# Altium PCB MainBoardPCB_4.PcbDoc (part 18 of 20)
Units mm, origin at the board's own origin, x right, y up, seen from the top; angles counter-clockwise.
Board outline 333.63 x 349.38 mm, 16 copper layers (L1, L2 (GND), L3 (Sign), L4 (GND), L5 (Sign), L6 (PWR/GND), L7(PWR/GND), L8 (Plane_GND), L9 (PWR/GND), L10 (PWR/GND), L11 (PWR/GND), L12 (Sign), L13 (GND), L14 (Sign), L15 (GND), L16), stack 2.502 mm thick; 2205 components, 1648 nets, 8314 pads, 3172 vias.
Unrouted connection lines stored in the file: 5141.
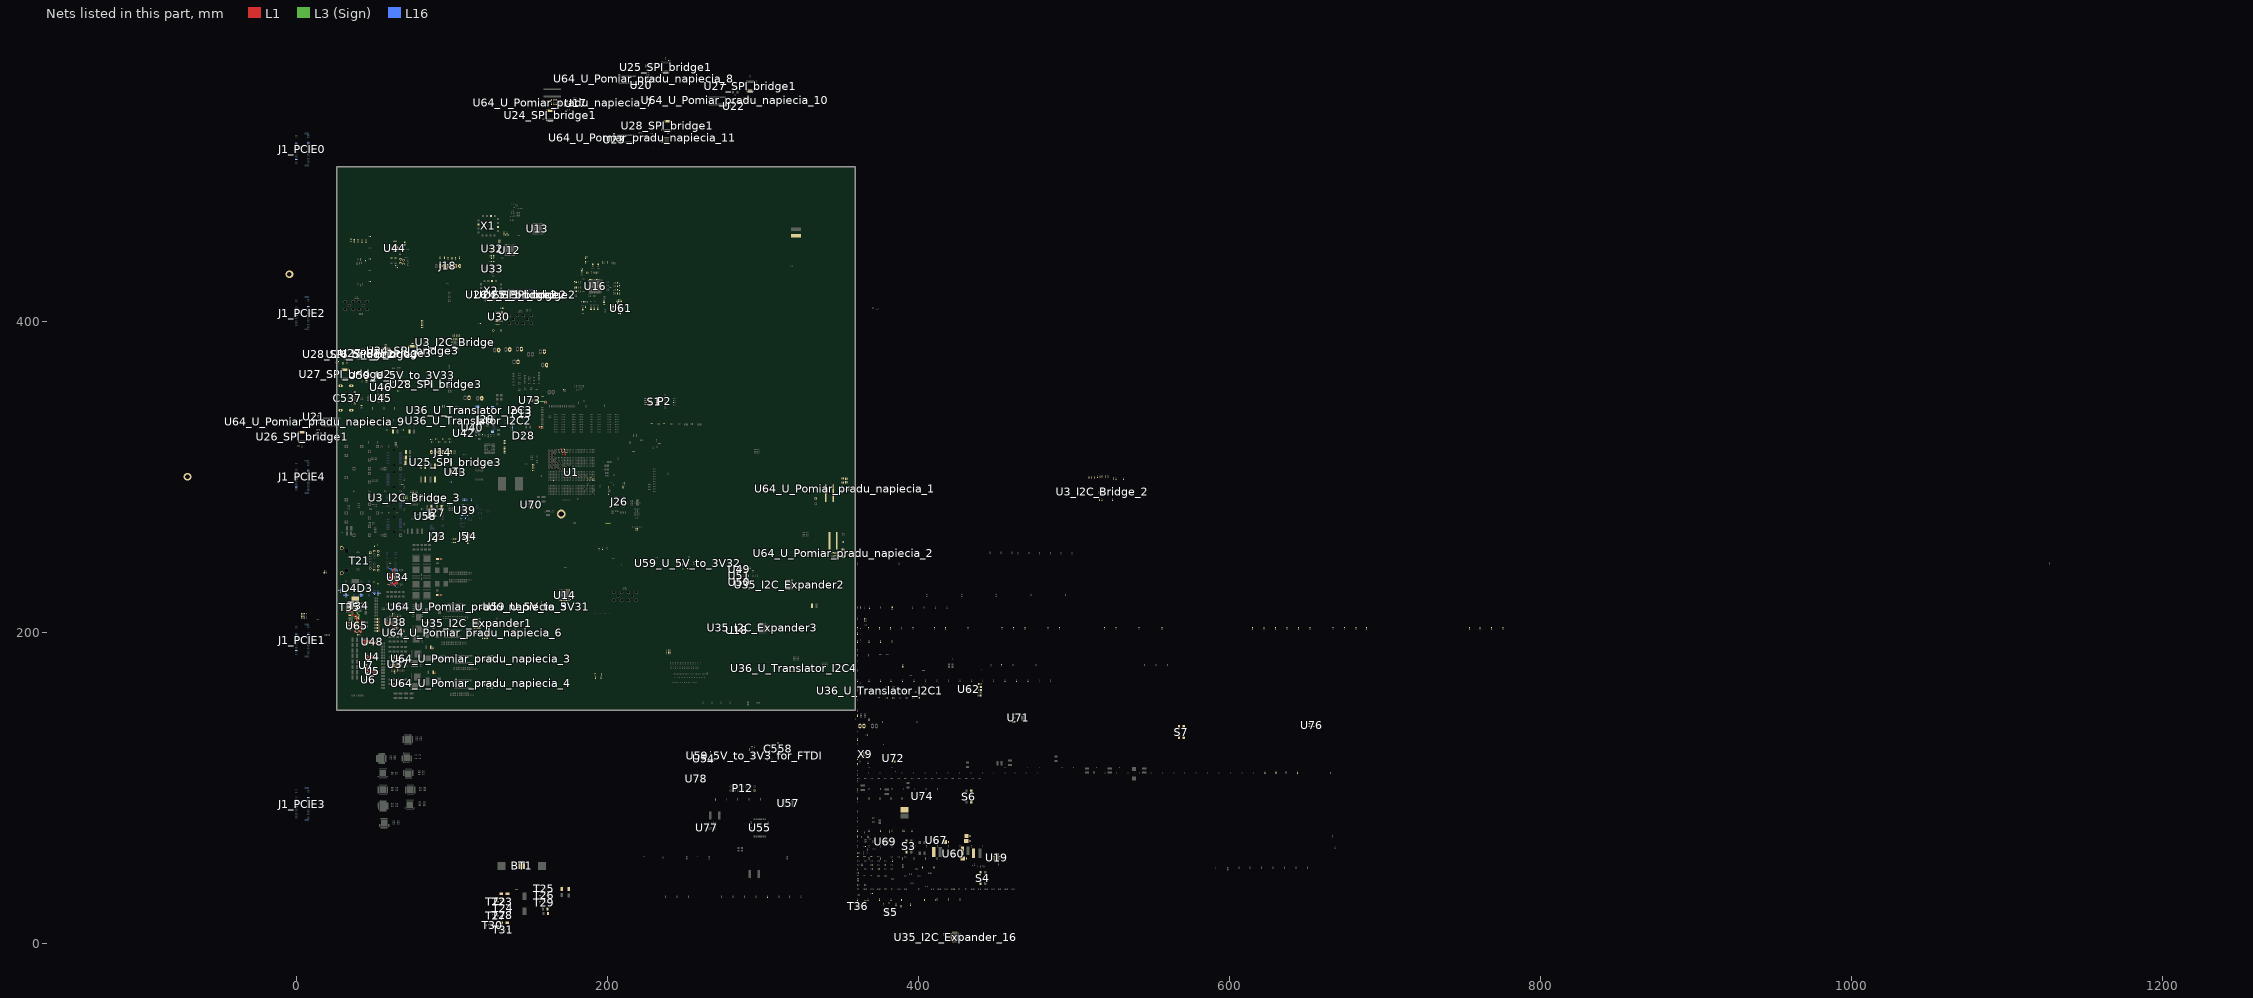
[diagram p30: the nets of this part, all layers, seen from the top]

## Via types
v1: diameter 0.5, hole 0.2, L1 to L16, tented both sides, 1153 vias
v2: diameter 0.5/0.35/0.35/0.35/0.35/0.35/0.35/0.35/0.35/0.35/0.35/0.35/0.35/0.35/0.35/0.5 (per signal layer), hole 0.2, L1 to L16, tented both sides, 548 vias
v3: diameter 0.5, hole 0.2, L1 to L16, 522 vias
v4: diameter 0.5/0.35/0.35/0.35/0.35/0.35/0.35/0.35/0.35/0.35/0.35/0.35/0.35/0.35/0.35/0.5 (per signal layer), hole 0.15, L1 to L16, tented both sides, 266 vias
v5: diameter 0.8, hole 0.4, L1 to L16, tented both sides, 164 vias
v6: diameter 0.35/0/0.35 (per signal layer), hole 0.127, L1 to L3 (Sign), tented both sides, 132 vias
v7: diameter 2.54, hole 1.02, L1 to L16, 125 vias
v8: diameter 1.4, hole 0.5, L1 to L16, tented both sides, 80 vias
v9: diameter 0.35, hole 0.127, L1 to L2 (GND), tented both sides, 36 vias
v10: diameter 0.4, hole 0.2, L1 to L16, 16 vias
v11: diameter 0.25, hole 0.2, L1 to L16, 16 vias
v12: diameter 5, hole 3, L1 to L16, 15 vias
v13: diameter 0.3, hole 0.2, L1 to L16, 15 vias
v14: diameter 0.45, hole 0.15, L1 to L16, 12 vias
v15: diameter 0.5/0.35/0.35/0.35/0.35/0.35/0.35/0.35/0.35/0.35/0.35/0.35/0.35/0.35/0.35/0.45 (per signal layer), hole 0.15, L1 to L16, tented both sides, 10 vias
v16: diameter 0.2/0/0.2 (per signal layer), hole 0.1, L1 to L3 (Sign), tented both sides, 9 vias
v17: diameter 0.4, hole 0.1, L1 to L16, 7 vias
v18: diameter 0.5, hole 0.2, L3 (Sign) to L6 (PWR/GND), tented both sides, 6 vias
v19: diameter 1.65, hole 1.65, L1 to L16, 6 vias
v20: diameter 1.15, hole 1.15, L1 to L16, 6 vias
v21: diameter 0.35/0/0.35 (per signal layer), hole 0.127, L14 (Sign) to L16, tented both sides, 5 vias
v22: diameter 0.2, hole 0.1, L1 to L16, 4 vias
v23: diameter 0.4, hole 0.2, L1 to L16, tented both sides, 2 vias
v24: diameter 0.4, hole 0.15, L1 to L16, 2 vias
v25: diameter 0.508, hole 0.127, L1 to L2 (GND), 2 vias
v26: diameter 0.508, hole 0.127, L2 (GND) to L3 (Sign), 2 vias
v27: diameter 0.5/0.35/0.35/0.35/0.35/0.35/0.35/0.35/0.35/0.35/0.35/0.35/0.35/0.35/0.35/0.5 (per signal layer), hole 0.15, L1 to L16, 2 vias
v28: diameter 0.35, hole 0.127, L3 (Sign) to L6 (PWR/GND), tented both sides, 2 vias
v29: diameter 5.5, hole 3.5, L1 to L16, 1 vias
v30: diameter 0.5/0.35/0.35/0.35/0.35/0.35/0.35/0.35/0.35/0.35/0.35/0.35/0.35/0.35/0.35/0.5 (per signal layer), hole 0.2, L1 to L16, 1 vias
v31: diameter 0.35/0.35/0.35 (per signal layer), hole 0.127, L1 to L3 (Sign), tented both sides, 1 vias
v32: diameter 0.45/0/0.45 (per signal layer), hole 0.15, L1 to L3 (Sign), tented both sides, 1 vias
v33: diameter 0.45/0/0.45 (per signal layer), hole 0.2, L14 (Sign) to L16, tented both sides, 1 vias
v34: diameter 0.35, hole 0.127, L2 (GND) to L3 (Sign), 1 vias
v35: diameter 0.35, hole 0.127, L1 to L2 (GND), 1 vias

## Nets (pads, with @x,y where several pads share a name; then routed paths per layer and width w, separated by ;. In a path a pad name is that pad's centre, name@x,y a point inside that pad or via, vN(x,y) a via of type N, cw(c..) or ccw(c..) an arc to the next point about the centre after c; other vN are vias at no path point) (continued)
Interrupt20: R735.2 U1.AD5 U64_U_Pomiar_pradu_napiecia_11.3
  other v2: 185.397,292.539
LED_0: R329.1 U39.47
LED_0_RJ: R329.2 T21.17
LED_1: R330.1 U39.46
LED_1_RJ: R330.2 T21.18
LED_2: R331.1 U39.45
LED_2_RJ: R331.2 T21.19
LED_3: R332.2 U39.39
LED_3_RJ: R332.1 T21.20
Logic_Out_KEY: R649.2 T26.3
LTC6952_1_CP_Out: C46.2 R77.2 U12.43 X1.2
LTC6952_1_REF_N: C53.1 R81.2 U12.46
LTC6952_1_REF_P: C54.1 R81.1 U12.45
LTC6952_1_Temp: R607.2 U12.49
LTC6952_1_VCO_N: C334.2 R532.2 U12.38
LTC6952_1_VCO_P: R533.1 U12.37
LTC6952_2_REF_N: C42.2 U13.46
LTC6952_2_REF_P: C41.2 U13.45
LTC6952_2_REF_SMA_N: C42.1 J3.2 R75.1
LTC6952_2_REF_SMA_P: C41.1 J2.2 R75.2
LTC6952_2_Temp: R736.2 U13.49
LTC6952_3_REF_N: C44.2 U14.46
LTC6952_3_REF_P: C43.2 U14.45
LTC6952_3_REF_SMA_N: C44.1 J5.2 R76.1
LTC6952_3_REF_SMA_P: C43.1 J4.2 R76.2
LTC6952_3_Temp: R765.2 U14.49
MDC: U39.16
MDIO: R333.2 U39.17
MIO_0: R768.2 U1.H17
  other v2: 169.397,304.539
MIO_1: R769.2
MIO_2: R770.2 U1.A20
  other v2: 162.397,307.539
MIO_3: R771.2 U1.D19
  other v2: 165.397,306.539
MIO_4: R772.2 U1.J17
  other v2: 170.397,304.539
MIO_5: R773.2 U1.C19
  other v2: 164.397,306.539
MIO_6: R774.2 U1.D20
  other v2: 165.397,307.539
MIO_7: R775.2 U1.E19
  other v2: 166.397,306.539
MIO_8: R776.2 U1.E20
  other v2: 166.397,307.539
MIO_9: R777.2 U1.F20
  other v2: 167.397,307.539
MIO_10: R778.2 U1.F18
  other v2: 167.397,305.539
MIO_11: R779.2 U1.G18
  other v2: 168.397,305.539
MIO_12: R780.2 U1.H18
  other v2: 169.397,305.539
MIO_13: R87.1 U1.G19
  other v2: 168.397,306.539
MIO_14: R88.1 U1.E18
  other v2: 166.397,305.539
MIO_15: R89.1 U1.J19
  other v2: 170.397,306.539
MIO_16: R90.1 U1.K17
  other v2: 171.397,304.539
MIO_17: R91.1 U1.C18
  other v2: 164.397,305.539
MIO_18: R92.1 U1.K18
  other v2: 171.397,305.539
MIO_19: R93.1 U1.K16
  other v2: 171.397,303.539
MIO_20: R94.1
MIO_21: R95.1 U1.H19
  other v2: 169.397,306.539
MIO_22: R96.1 U1.F17
  other v2: 167.397,304.539
MIO_23: R781.2 U1.K19
  other v2: 171.397,306.539
MIO_24: R782.2 U1.A18
  other v2: 162.397,305.539
MIO_25: R783.2 U1.B18
  other v2: 163.397,305.539
MIO_26: R784.2 U1.B20
  other v2: 163.397,307.539
MIO_27: R785.2 U1.B21
  other v2: 163.397,308.539
MIO_28: R786.2 U1.A21
  other v2: 162.397,308.539
MIO_29: R787.2 U1.D21
  other v2: 165.397,308.539
MIO_30: R788.2 U1.C21
  other v2: 164.397,308.539
MIO_31: R789.2 U1.A22
  other v2: 162.397,309.539
MIO_32: R790.2 U1.G20
  other v2: 168.397,307.539
MIO_33: R791.2 U1.C22
  other v2: 164.397,309.539
MIO_34: R792.2 U1.B24
  other v2: 163.397,311.539
MIO_35: R793.2 U1.B23
  other v2: 163.397,310.539
MIO_36: R794.2 U1.D22
  other v2: 165.397,309.539
MIO_37: R795.2 U1.F21
  other v2: 167.397,308.539
MIO_38: R796.2 U1.C23
  other v2: 164.397,310.539
MIO_39: R101.1 U1.E22
  other v2: 166.397,309.539
MIO_40: R102.1 U1.C24
  other v2: 164.397,311.539
MIO_41: R103.1 U1.D24
  other v2: 165.397,311.539
MIO_42: R104.1 U1.E23
  other v2: 166.397,310.539
MIO_43: R797.2 U1.F22
  other v2: 167.397,309.539
MIO_44: R798.2 U1.E24
  other v2: 166.397,311.539
MIO_45: R799.2 U1.F23
  other v2: 167.397,310.539
MIO_46: R105.1 U1.K20
  other v2: 171.397,307.539
MIO_47: R107.1 U1.K21
  other v2: 171.397,308.539
MIO_48: R108.1 U1.J21
  other v2: 170.397,308.539
MIO_49: R110.1 U1.G21
  other v2: 168.397,308.539
MIO_50: R111.1 U1.J20
  other v2: 170.397,307.539
MIO_51: R112.1 U1.H21
  other v2: 169.397,308.539
MIO_52: R362.1 U1.A24
  other v2: 162.397,311.539
MIO_53: R800.2 U1.B25
  other v2: 163.397,312.539
MIO_54: R115.1 U1.A23
  other v2: 162.397,310.539
MIO_55: R801.2 U1.B26
  other v2: 163.397,313.539
MIO_56: R116.1 U1.A25
  other v2: 162.397,312.539
MIO_57: R117.1 U1.A26
  other v2: 162.397,313.539
MIO_58: R118.1 U1.A28
  other v2: 162.397,315.539
MIO_59: R119.1 U1.A27
  other v2: 162.397,314.539
MIO_60: R120.1 U1.C26
  other v2: 164.397,313.539
MIO_61: R121.1 U1.B29
  other v2: 163.397,316.539
MIO_62: R122.1 U1.B28
  other v2: 163.397,315.539
MIO_63: R802.2 U1.A29
  other v2: 162.397,316.539
MIO_64: R803.2 U1.B30
  other v2: 163.397,317.539
MIO_65: R804.2 U1.D25
  other v2: 165.397,312.539
MIO_66: R805.2 U1.C27
  other v2: 164.397,314.539
MIO_67: R806.2 U1.C28
  other v2: 164.397,315.539
MIO_68: R807.2 U1.C29
  other v2: 164.397,316.539
MIO_69: R808.2 U1.D27
  other v2: 165.397,314.539
MIO_70: R809.2 U1.D26
  other v2: 165.397,313.539
MIO_71: R810.2 U1.D30
  other v2: 165.397,317.539
MIO_72: R811.2 U1.E27
  other v2: 166.397,314.539
MIO_73: R812.2 U1.E30
  other v2: 166.397,317.539
MIO_74: R813.2 U1.E29
  other v2: 166.397,316.539
MIO_75: R814.2 U1.D29
  other v2: 165.397,316.539
MIO_76: R815.2 U1.E28
  other v2: 166.397,315.539
MIO_77: R816.2 U1.E25
  other v2: 166.397,312.539
MIO_GPIO_0_12: J15.2 R780.1
MIO_GPIO_0_23: J16.2 R98.1 R781.1
MIO_GPIO_1_38: J17.2 R796.1
MIO_GPIO_2_66: J19.2 R805.1
MIO_GPIO_2_70: J20.2 R809.1
MIO_GPIO_2_73: J22.2 R812.1
MIO_GPIO_2_74: J23.2 R813.1 U36_U_Translator_I2C2.8
MIO_GPIO_2_75: J24.2 R814.1 U36_U_Translator_I2C3.8
MODE: R669.2 R670.1 U65.2 | length 3.6
  L1 w0.254: R670.1@37.668,200.838 38.26,200.838 ; U65.2@38.26,202.478 38.26,200.838 ; R669.2@38.887,199.931 38.537,199.931 38.26,200.208 38.26,200.838
NetBT1_2: BT1.2 R650.1 T22.2
NetC36_1: C36.1 R52.2 R54.2 | length 3.4
  L1 w0.5: R52.2@157.837,331.433 156.878,331.433 C36.1@156.346,331.965 156.903,332.522 R54.2@157.837,332.522
NetC45_2: C45.2 R77.1
NetC78_2: C78.2 U16.7
NetC79_2: C79.2 U16.38
NetC80_2: C80.2 U16.48
NetC91_1: C91.1 U16.39
NetC96_1: C96.1 U16.47
NetC207_2: C207.2 C208.1 L3.2
NetC209_2: C209.2 C210.1 L4.2
NetC211_2: C211.2 C212.1 L5.2
NetC213_2: C213.2 C214.1 L6.2
NetC215_2: C215.2 C216.1 L7.2
NetC217_2: C217.2 C218.1 L8.2
NetC277_2: C277.2
NetC278_2: C278.2
NetC289_2: C289.2
NetC290_2: C290.2
NetC301_2: C301.2
NetC302_2: C302.2
NetC320_1: C320.1 U30.9
NetC321_1: C321.1 U30.10
NetC322_2: C322.2 U30.3 X3.1
NetC323_2: C323.2 U30.2 X3.2
NetC334_1: C334.1 X1.10
NetC335_2: C335.2 R532.1 R533.2
NetC341_1: C341.1 J26.1
NetC351_2: C351.2 R268.2 U34.3 | length 4.2
  L1 w0.254: R268.2@59.692,237.714 60.97,237.714 61.118,237.565 61.118,236.791 C351.2@61.146,236.764 61.151,236.764 61.776,236.139 U34.3@62.822,236.139
NetC356_2: C356.2 R272.2 R277.1 R278.1 U34.2 U34.4 U34.7 U34.9 U34.32 | length 23.6
  L1 w0.254: U34.4@62.822,235.639 61.694,235.639 61.667,235.666 60.285,235.666 60.109,235.49 60.109,235.185 R272.2@60.156,235.139 60.206,235.139 60.479,234.866 60.479,234.745 60.783,234.441 60.783,233.982 60.926,233.839 C356.2@60.931,233.839 61.589,233.839 61.99,233.437 v17(62.009,233.437) 62.049,233.437 62.347,233.139 U34.9@63.322,233.139 ; U34.2@62.822,236.639 62.481,236.639 62.057,237.063 62.057,237.421 v17@62.125,237.489 ; U34.32@63.322,237.639 63.322,237.703 63.32,237.705 62.341,237.705 v17@62.125,237.489 ; R278.1@63.439,240.856 63.077,240.856 62.085,239.863 62.085,237.528 v17@62.125,237.489
  L16 w0.254: v17(62.085,237.489) 62.085,237.449 62.009,237.373 v17(62.009,233.437) 62.009,231.673 v22(64.365,229.317)
NetC357_2: C357.2 U34.13 U34.28 | length 10.4
  L1 w0.254: v22(64.511,231.163) 64.583,231.235 64.816,231.235 65.315,231.734 65.315,232.984 65.32,232.989 65.32,233.137 U34.13@65.322,233.139 ; U34.28@65.322,237.639 v17(65.322,238.22)
  L16 w0.254: v22(64.511,231.163) 64.949,231.601 64.949,237.847 v17(65.322,238.22)
NetC471_2: C471.2 T21.12
NetC472_2: C472.2 T21.6
NetC473_2: C473.2 T21.1
NetC474_2: C474.2 T21.7
NetC475_2: T21.S1
NetC476_2: T21.S2
NetC532_1: C532.1 U44.14
NetC533_1: C533.1 U44.15
NetC534_1: C534.1 U44.16
NetC537_1: C537.1 FB26.2
NetC537_4: C537.4 FB27.2
NetC537_Z1: C537.Z1 FB28.1
NetC549_2: C549.2 R687.1 | length 1.1
  L1 w0.254: C549.2@61.948,212.229 61.951,212.227 61.951,211.171 R687.1@61.953,211.169
NetC558_Z1: C558.Z1 C558.Z2
NetC568_2: C568.2 FB33.1 R433.2 U60.10 U60.11 U60.12 U60.13 U60.14
NetC571_1: C571.1 U60.7
NetC573_1: C573.1 R436.1 R437.2 U61.16
NetC577_1: C577.1 R438.1 R439.2 U61.10
NetC578_2: C578.2 U61.7
NetC579_2: C579.2 U61.19
NetC581_2: C581.2 C582.2 C583.2 FB34.2 R442.2 U62.1 U62.2 U62.3
NetC584_2: C584.2 R445.2 U62.7
NetC588_1: C588.1 R543.2
NetC588_2: C588.2 C589.1 R545.2
NetC591_2: C591.2 C592.2 FB37.2 X9.4
NetC597_2: C597.2 R140.1 U65.17 | length 3.4
  L1 w0.254: C597.2@34.722,206.35 34.722,205.41 R140.1@34.747,205.384 35.433,205.384 36,204.818 U65.17@36.92,204.818
NetC603_1: C603.1 R113.1 R114.2 U19.20
NetC604_1: C604.1 U19.25
NetC605_1: C605.1 R212.1 R214.2 U19.21
NetC612_1: C612.1 R216.2 R218.2 U19.22
NetC616_1: C616.1 R220.1 R274.2 U19.19
NetC633_2: C633.2 R613.1 | length 2.3
  L1 w0.254: R613.1@90.765,247.284 C633.2@93.052,247.284
NetC634_2: C634.2 R615.2 U34.11 U34.30 | length 14.8
  L1 w0.254: v17(61.056,231.693) 63.519,231.693 64.315,232.489 64.315,232.984 64.32,232.989 64.32,233.137 U34.11@64.322,233.139 ; v17(64.297,238.715) 64.32,238.692 U34.30@64.322,237.639 U34.30@64.322,237.639
  L16 w0.254: v17(61.056,231.693) R615.2@61.056,234.739 61.042,234.753 61.042,235.71 C634.2@61.028,235.724 61.028,235.729 61.301,236.002 61.392,236.002 61.525,236.135 61.525,237.705 62.535,238.715 v17(64.297,238.715)
NetC635_2: C635.2 R615.1 | length 1
  L16 w0.254: C635.2@60.062,235.724 60.109,235.677 60.109,234.785 R615.1@60.156,234.739
NetC636_2: C636.2 R616.1 | length 2.2
  L1 w0.254: R616.1@90.717,224.031 C636.2@92.942,224.031
NetC637_2: C637.2 R288.1 | length 1
  L1 w0.254: 87.033,189.468 87.568,189.468 C637.2@87.909,189.81
NetC638_2: C638.2 R298.1 | length 1.1
  L1 w0.254: 88.405,173.59 88.411,173.596 88.938,173.596 C638.2@89.332,173.99
NetC643_2: C643.2 R623.1 | length 1.1
  L1 w0.254: C643.2@63.12,173.949 R623.1@63.12,175.007
NetC644_2: C644.2 R624.1 | length 1
  L1 w0.254: R624.1@63.175,184.21 C644.2@63.175,185.176
NetC645_2: C645.2 R306.1 | length 0.9
  L1 w0.254: 87.566,203.543 87.564,203.54 87.564,203.257 C645.2@87.964,202.857
NetC646_2: C646.2 R316.1 | length 1.1
  L1 w0.254: C646.2@84.502,207.488 85.052,206.938 85.052,206.654
NetC649_2: C649.2
NetC651_2: C651.2
NetC652_2: C652.2 R631.1
NetC653_2: C653.2
NetC655_1: C655.1 U49.6
NetC656_1: C656.1 U50.6
NetC657_1: C657.1 U51.6
NetC674_2: C674.2 FB45.1 R644.2 U69.10 U69.11 U69.12 U69.13 U69.14
NetC677_2: C677.2
NetC678_2: C678.2 R652.2 R654.2 T25.1 T29.3
NetC679_2: C679.2 D22.1 D23.1
NetC680_2: C680.2 R656.1 R657.1 T30.1
NetC693_1: C693.1 L22.1 T34.1 T34.2 T34.3 T35.5 U65.12 | length 3.2
  L1 w0.254: U65.12@39.26,206.158 39.26,207.104 39.98,207.823 C693.1@39.98,209.037
NetC693_2: C693.2 D26.1 R665.1 | length 6.9
  L1 w0.254: R665.1@39.014,209.828 39.025,209.817 C693.2@39.98,209.817
  L1 w0.5: D26.1@34.353,210.921 35.856,210.921 36.25,211.315 38.427,211.315 39.014,210.728 R665.1@39.014,209.828
NetC701_1: C701.1 R667.2 | length 2.9
  L1 w0.254: C701.1@41.097,200.121 41.676,200.121 42.078,200.524 R667.2@42.078,202.265
NetC701_2: C701.2 C702.2 U65.5 | length 2.7
  L1 w0.254: U65.5@39.76,202.478 39.76,201.311 C702.2@40.17,200.901 C701.2@41.097,200.901
NetC703_2: C703.2 U65.7 | length 1.7
  L1 w0.254: U65.7@40.6,203.818 41.292,203.818 41.38,203.73 41.759,203.73 C703.2@42.127,204.097
NetC706_1: C706.1 R671.1 R672.2 U70.16
NetC710_1: C710.1 R673.1 R674.2 U70.10
NetC711_2: C711.2 U70.7
NetC712_2: C712.2 U70.19
NetC713_2: C713.2 U71.3 X1.14
NetC715_2: C715.2
NetC716_2: C716.2
NetC717_2: C717.2
NetC718_2: C718.2
NetC719_2: C719.2 U69.7
NetC724_1: C724.1 R384.1
NetC725_1: C725.1 R385.1
NetC726_1: C726.1 R484.1
  other v29: 170.471,276.121
NetC727_1: C727.1 R485.1
NetC790_1: C790.1 U76.3
NetD5_1: D5.1 R716.1
NetD5_2: D5.2 U43.14
NetD6_1: D6.1 R717.1
NetD6_2: D6.2 U43.13
NetD7_1: D7.1 R718.1
NetD7_2: D7.2 D9.2 U43.12
NetD8_1: D8.1 R719.1
NetD8_2: D8.2 U43.11
NetD9_1: D9.1 R720.1
NetD10_1: D10.1 R368.1
NetD10_2: D10.2 U44.12
NetD11_2: D11.2 R370.1 S4.1 S4.2 U44.7
NetD12_2: D12.2 R369.1 S3.1 S3.2 U44.6
NetD16_1: D16.1 L13.1 U19.5
NetD16_2: D16.2 U19.6
NetD17_1: D17.1 L16.1 U19.4
NetD17_2: D17.2 U19.3
NetD18_1: D18.1 L17.1 U19.2
NetD18_2: D18.2 U19.1
NetD19_1: D19.1 L18.1 U19.7
NetD19_2: D19.2 U19.8
NetD20_1: D20.1 D21.1 R647.1
NetD20_2: D20.2 T23.3
NetD21_2: D21.2 T27.3
NetD28_2: D28.2 R276.2
NetFB29_2: FB29.2 J28.10 J28.11 J28.12 J28.13
NetJ30_1: J30.1 R283.2
NetJ30_2: J30.2 R286.2
NetL15_2: L15.2 U19.24
NetP3_1: P3.1 U44.11
NetP4_2: P4.2 U44.10
NetP12_13: P12.13 R730.1 U78.1
NetP13_1: P13.1 R675.2
NetP13_3: P13.3 R737.1
NetR3_I2C_Bridge_1: R3_I2C_Bridge.1 U3_I2C_Bridge.17
NetR3_I2C_Bridge_2_1: R3_I2C_Bridge_2.1 U3_I2C_Bridge_2.17
NetR3_I2C_Bridge_3_1: R3_I2C_Bridge_3.1 R176.1 R180.1 R185.1 R189.1 R194.1 R198.1 R203.1 R207.1 R213.1 R221.1 R538.1 U3_I2C_Bridge.19 U3_I2C_Bridge_3.17 U58.13 U64_U_Pomiar_pradu_napiecia_7.5 U64_U_Pomiar_pradu_napiecia_8.5 U64_U_Pomiar_pradu_napiecia_9.5 U64_U_Pomiar_pradu_napiecia_10.5 U64_U_Pomiar_pradu_napiecia_11.5
NetR4_I2C_Bridge_1: R4_I2C_Bridge.1 U3_I2C_Bridge.16
NetR4_I2C_Bridge_2_1: R4_I2C_Bridge_2.1 U3_I2C_Bridge_2.16
NetR4_I2C_Bridge_3_1: R4_I2C_Bridge_3.1 R177.1 R181.1 R186.1 R190.1 R195.1 R199.1 R204.1 R208.1 R215.1 R222.1 R427.1 U3_I2C_Bridge.20 U3_I2C_Bridge_3.16 U58.14 U64_U_Pomiar_pradu_napiecia_7.4 U64_U_Pomiar_pradu_napiecia_8.4 U64_U_Pomiar_pradu_napiecia_9.4 U64_U_Pomiar_pradu_napiecia_10.4 U64_U_Pomiar_pradu_napiecia_11.4
NetR5_I2C_Bridge_1: R5_I2C_Bridge.1 U3_I2C_Bridge.15
NetR5_I2C_Bridge_2_1: R5_I2C_Bridge_2.1 U3_I2C_Bridge_2.15
NetR5_I2C_Bridge_3_1: R5_I2C_Bridge_3.1 U3_I2C_Bridge_3.15 U35_I2C_Expander3.8
NetR6_I2C_Bridge_1: R6_I2C_Bridge.1 U3_I2C_Bridge.14
NetR6_I2C_Bridge_2_1: R6_I2C_Bridge_2.1 U3_I2C_Bridge_2.14
NetR6_I2C_Bridge_3_1: R6_I2C_Bridge_3.1 U3_I2C_Bridge_3.14 U35_I2C_Expander3.9
NetR7_I2C_Bridge_1: R7_I2C_Bridge.1 U3_I2C_Bridge.13
NetR7_I2C_Bridge_2_1: R7_I2C_Bridge_2.1 U3_I2C_Bridge_2.13
NetR7_I2C_Bridge_3_1: R7_I2C_Bridge_3.1 R130.1 U3_I2C_Bridge_3.13
NetR8_I2C_Bridge_1: R8_I2C_Bridge.1 U3_I2C_Bridge.12
NetR8_I2C_Bridge_2_1: R8_I2C_Bridge_2.1 U3_I2C_Bridge_2.12
NetR8_I2C_Bridge_3_1: R8_I2C_Bridge_3.1 R131.1 U3_I2C_Bridge_3.12
NetR9_I2C_Bridge_2_1: R9_I2C_Bridge_2.1 U3_I2C_Bridge_2.11
NetR9_I2C_Bridge_3_1: R9_I2C_Bridge_3.1 R22.1 R389.1 R457.1 R465.1 R563.1 R567.1 R571.1 R575.1 R579.1 R583.1 R587.1 R591.1 R593.1 R597.1 U3_I2C_Bridge_3.11 U35_I2C_Expander1.8 U35_I2C_Expander2.8 U64_U_Pomiar_pradu_napiecia_1.5 U64_U_Pomiar_pradu_napiecia_2.5 U64_U_Pomiar_pradu_napiecia_3.5 U64_U_Pomiar_pradu_napiecia_4.5 U64_U_Pomiar_pradu_napiecia_5.5 U64_U_Pomiar_pradu_napiecia_6.5 U72.5
NetR10_I2C_Bridge_2_1: R10_I2C_Bridge_2.1 U3_I2C_Bridge_2.10
NetR10_I2C_Bridge_3_1: R10_I2C_Bridge_3.1 R24.1 R390.1 R459.1 R466.1 R564.1 R568.1 R572.1 R576.1 R580.1 R584.1 R588.1 R592.1 R594.1 R598.1 U3_I2C_Bridge_3.10 U35_I2C_Expander1.9 U35_I2C_Expander2.9 U64_U_Pomiar_pradu_napiecia_1.4 U64_U_Pomiar_pradu_napiecia_2.4 U64_U_Pomiar_pradu_napiecia_3.4 U64_U_Pomiar_pradu_napiecia_4.4 U64_U_Pomiar_pradu_napiecia_5.4 U64_U_Pomiar_pradu_napiecia_6.4 U72.4
NetR12_1: R12.1 R19.2 U5.5 | length 4.2
  L1 w0.2: R19.2@44.801,174.289 R12.1@45.844,174.289 45.844,174.314 46.28,174.75 U5.5@47.56,174.75 46.345,174.75
NetR14_2: R14.2 R16.2 R22.2 R24.2 U72.2
NetR15_1: R15.1 R23.2 U4.5 | length 2.9
  L1 w0.2: R23.2@44.92,183.563 R15.1@45.94,183.563 45.94,183.667 46.345,184.071 U4.5@47.56,184.071
NetR17_1: R17.1 R25.2 U4.4 | length 2.9
  L1 w0.2: R25.2@44.92,185.074 R17.1@45.94,185.074 45.94,184.98 46.349,184.571 U4.4@47.56,184.571
NetR18_2: R18.2 U4.10 | length 1.4
  L1 w0.2: U4.10@49.86,184.071 50.307,184.071 50.707,184.471 R18.2@51.11,184.471
NetR20_1: R20.1 R26.2 U5.4 | length 4.2
  L1 w0.2: R26.2@44.801,175.686 R20.1@45.822,175.686 46.258,175.25 U5.4@47.56,175.25 46.349,175.25
NetR21_2: R21.2 U5.10 | length 1.9
  L1 w0.2: U5.10@49.86,174.75 50.762,174.75 51.138,175.125 R21.2@51.6,175.125
NetR27_2: R27.2 U6.C1
NetR28_2: R28.2 U7.C1
NetR149_1: R149.1 R159.2 U65.20 | length 2.2
  L1 w0.254: R159.2@34.773,203.149 35.891,203.149 36.059,203.318 U65.20@36.92,203.318
NetR150_1: R150.1 R160.2 U65.6 | length 8.3
  L1 w0.254: U65.6@40.6,203.318 41.282,203.318 ; v6(41.123,202.654) 41.282,202.814 41.282,203.318 ; R160.2@42.078,203.203 41.397,203.203 41.282,203.318 ; R150.1@42.202,206.468 v6(42.202,207.35)
  L3 (Sign) w0.254: v6(41.123,202.654) 42.202,203.733 v6(42.202,207.35)
NetR174_2: R174.2 R175.2 R176.2 R177.2 U64_U_Pomiar_pradu_napiecia_7.2
NetR178_2: R178.2 R179.2 R180.2 R181.2 U64_U_Pomiar_pradu_napiecia_7.1
NetR182_2: R182.2 U17.C1
NetR183_2: R183.2 R184.2 R185.2 R186.2 U64_U_Pomiar_pradu_napiecia_8.2
NetR187_2: R187.2 R188.2 R189.2 R190.2 U64_U_Pomiar_pradu_napiecia_8.1
NetR191_2: R191.2 U20.C1
NetR192_2: R192.2 R193.2 R194.2 R195.2 U64_U_Pomiar_pradu_napiecia_9.2
NetR196_2: R196.2 R197.2 R198.2 R199.2 U64_U_Pomiar_pradu_napiecia_9.1
NetR200_2: R200.2 U21.C1
NetR201_2: R201.2 R202.2 R203.2 R204.2 U64_U_Pomiar_pradu_napiecia_10.2
NetR205_2: R205.2 R206.2 R207.2 R208.2 U64_U_Pomiar_pradu_napiecia_10.1
NetR209_2: R209.2 U22.C1
NetR210_2: R210.2 R211.2 R213.2 R215.2 U64_U_Pomiar_pradu_napiecia_11.2
NetR217_2: R217.2 R219.2 R221.2 R222.2 U64_U_Pomiar_pradu_napiecia_11.1
NetR223_I2C_Bridge_2_1: R223_I2C_Bridge_2.1 U3_I2C_Bridge_2.8
NetR224_I2C_Bridge_2_1: R224_I2C_Bridge_2.1 U3_I2C_Bridge_2.7
NetR225_I2C_Bridge_2_1: R225_I2C_Bridge_2.1 U3_I2C_Bridge_2.6
NetR226_I2C_Bridge_2_1: R226_I2C_Bridge_2.1 U3_I2C_Bridge_2.5
NetR227_I2C_Bridge_2_1: R227_I2C_Bridge_2.1 U3_I2C_Bridge_2.4 U35_I2C_Expander_16.8
NetR228_2: R228.2 U23.C1
NetR229_2: R229.2 R230.2 R457.2 R459.2 U64_U_Pomiar_pradu_napiecia_1.2
NetR231_SPI_bridge3_1: R231_SPI_bridge3.1 U24_SPI_bridge3.11
NetR231_SPI_bridge3_2: R231_SPI_bridge3.2 U24_SPI_bridge3.15
NetR232_SPI_bridge1_2: R232_SPI_bridge1.2 U24_SPI_bridge1.9
NetR232_SPI_bridge2_2: R232_SPI_bridge2.2 U24_SPI_bridge2.9
NetR232_SPI_bridge3_2: R232_SPI_bridge3.2 U24_SPI_bridge3.9
NetR233_SPI_bridge3_1: R233_SPI_bridge3.1 U24_SPI_bridge1.6 U25_SPI_bridge1.6 U25_SPI_bridge3.11 U26_SPI_bridge1.6 U27_SPI_bridge1.6 U28_SPI_bridge1.6
NetR234_SPI_bridge1_2: R234_SPI_bridge1.2 U25_SPI_bridge1.9
NetR234_SPI_bridge2_2: R234_SPI_bridge2.2 U25_SPI_bridge2.9
NetR234_SPI_bridge3_2: R234_SPI_bridge3.2 U25_SPI_bridge3.9
NetR235_SPI_bridge1_1: R235_SPI_bridge1.1 U26_SPI_bridge1.9
NetR235_SPI_bridge2_1: R235_SPI_bridge2.1 U26_SPI_bridge2.9
NetR235_SPI_bridge3_1: R235_SPI_bridge3.1 U26_SPI_bridge3.9
NetR237_SPI_bridge1_1: R237_SPI_bridge1.1 U27_SPI_bridge1.9
NetR237_SPI_bridge2_1: R237_SPI_bridge2.1 U27_SPI_bridge2.9
NetR237_SPI_bridge3_1: R237_SPI_bridge3.1 U27_SPI_bridge3.9
NetR238_SPI_bridge2_1: R238_SPI_bridge2.1 U27_SPI_bridge2.11
NetR238_SPI_bridge2_2: R238_SPI_bridge2.2 U27_SPI_bridge2.15
NetR238_SPI_bridge3_1: R238_SPI_bridge3.1 U27_SPI_bridge3.11
NetR238_SPI_bridge3_2: R238_SPI_bridge3.2 U27_SPI_bridge3.15
NetR239_SPI_bridge1_2: R239_SPI_bridge1.2 U28_SPI_bridge1.9
NetR239_SPI_bridge2_2: R239_SPI_bridge2.2 U28_SPI_bridge2.9
NetR239_SPI_bridge3_2: R239_SPI_bridge3.2 U28_SPI_bridge3.9
NetR240_SPI_bridge3_1: R240_SPI_bridge3.1 U28_SPI_bridge3.11
NetR240_SPI_bridge3_2: R240_SPI_bridge3.2 U28_SPI_bridge3.15
NetR241_1: R241.1 R242.1 U3_I2C_Bridge_2.22
NetR243_1: R243.1 R244.1 U3_I2C_Bridge_2.23
NetR263_2: R263.2 U33.16
NetR264_2: R264.2 U33.13
NetR265_2: R265.2 U33.15
NetR266_1: R266.1 R267.2 S5.1 S5.2 S5.3 S5.4
NetR269_2: R269.2 U18.C1
NetR272_1: R272.1 U34.5 | length 1.8
  L1 w0.254: R272.1@61.056,235.139 U34.5@62.822,235.139
NetR281_1: R281.1 R400.1 U3_I2C_Bridge_2.18
NetR284_2: R284.2 U19.17
NetR289_1: R289.1 U37.5 | length 1.4
  L1 w0.254: R289.1@61.781,179.317 U37.5@63.175,179.317
NetR293_2: R293.2 R294.2 U37.7 | length 2.4
  L1 w0.254: R294.2@61.781,177.317 R293.2@61.781,178.317 U37.7@63.175,178.317
NetR304_2: R304.2 R388.2 R389.2 R390.2 U72.1
NetR305_2: R305.2 U67.6
NetR307_1: R307.1 U38.5 | length 4.1
  L1 w0.254: R307.1@57.945,206.596 57.945,206.233 58.189,205.989 59.673,205.989 59.898,206.214 U38.5@61.453,206.214
NetR308_2: R308.2 U67.5
NetR309_2: R309.2 U67.4
NetR310_2: R310.2 R312.2 U38.7 | length 2.8
  L1 w0.254: R312.2@58.826,204.716 59.784,204.716 60.282,205.214 U38.7@61.453,205.214
NetR334_1: R334.1 U39.12
NetR339_1: R339.1 R341.2 U40.7
NetR342_1: R342.1 R344.2 U42.7
NetR358_1: R358.1 S1.8
NetR359_1: R359.1 S1.7
NetR360_1: R360.1 S1.6
NetR361_1: R361.1 S1.5
NetR366_2: R366.2 R498.1 R499.2 R692.2
NetR372_1: R372.1 R373.2 U44.2 U44.3
NetR379_2: R379.2 U45.24
NetR380_2: R380.2 U46.C1
NetR391_1: R391.1 R393.2 U49.7
  other v12: -69.975,300.045
NetR394_1: R394.1 R396.2 U50.7
NetR397_1: R397.1 R399.2 U51.7
NetR419_2: R419.2 R422.1 U54.1
NetR423_2: R423.2 U55.6
NetR424_2: R424.2 U55.14
NetR428_1: R428.1 U3_I2C_Bridge_2.20 U36_U_Translator_I2C1.5 U36_U_Translator_I2C2.5
  other v12: -4.475,430.276
NetR429_1: R429.1 U58.12
NetR430_5V_to_3V3_for_FTDI_1: R430_5V_to_3V3_for_FTDI.1 R432_5V_to_3V3_for_FTDI.2 U59_5V_to_3V3_for_FTDI.7
NetR430_U_5V_to_3V31_1: R430_U_5V_to_3V31.1 R432_U_5V_to_3V31.2 U59_U_5V_to_3V31.7
NetR430_U_5V_to_3V32_1: R430_U_5V_to_3V32.1 R432_U_5V_to_3V32.2 U59_U_5V_to_3V32.7
NetR430_U_5V_to_3V33_1: R430_U_5V_to_3V33.1 R432_U_5V_to_3V33.2 U59_U_5V_to_3V33.7
NetR431_5V_to_3V3_for_FTDI_1: R431_5V_to_3V3_for_FTDI.1 U59_5V_to_3V3_for_FTDI.5
NetR433_1: R433.1 R434.2 U60.9
NetR435_1: R435.1 R668.2 U69.4
NetR443_1: R443.1 R444.2 U62.6
NetR449_1: R449.1 R450.1 U3_I2C_Bridge.22
NetR451_1: R451.1 R452.1 U3_I2C_Bridge.23
NetR453_1: R453.1 R454.1 U3_I2C_Bridge.18
NetR455_1: R455.1 R456.1 U35_I2C_Expander1.13
NetR458_1: R458.1 R460.1 U35_I2C_Expander1.12
NetR461_2: R461.2 R463.2 R465.2 R466.2 U64_U_Pomiar_pradu_napiecia_1.1
NetR462_1: R462.1 R464.1 U35_I2C_Expander1.11
NetR467_2: R467.2 R468.2 R593.2 R594.2 U64_U_Pomiar_pradu_napiecia_2.2
NetR469_1: R469.1 R470.1 U3_I2C_Bridge_3.22
NetR471_1: R471.1 R472.1 U3_I2C_Bridge_3.23
NetR473_1: R473.1 R474.1 U3_I2C_Bridge_3.18
NetR475_1: R475.1 R476.1 U35_I2C_Expander3.13
NetR477_1: R477.1 R478.1 U35_I2C_Expander3.12
NetR479_1: R479.1 R480.1 U35_I2C_Expander3.11
NetR481_2: R481.2 U26_SPI_bridge3.13
NetR488_1: R488.1 T36.3 U32.2
NetR543_1: R543.1 X9.3
NetR544_1: R544.1 X9.1
NetR558_I2C_Bridge_2_1: R558_I2C_Bridge_2.1 U3_I2C_Bridge_2.3 U35_I2C_Expander_16.9
NetR561_2: R561.2 R562.2 R563.2 R564.2 U64_U_Pomiar_pradu_napiecia_3.2
NetR565_2: R565.2 R566.2 R567.2 R568.2 U64_U_Pomiar_pradu_napiecia_3.1
NetR569_2: R569.2 R570.2 R571.2 R572.2 U64_U_Pomiar_pradu_napiecia_4.2
NetR573_2: R573.2 R574.2 R575.2 R576.2 U64_U_Pomiar_pradu_napiecia_4.1
NetR577_2: R577.2 R578.2 R579.2 R580.2 U64_U_Pomiar_pradu_napiecia_5.2
NetR581_2: R581.2 R582.2 R583.2 R584.2 U64_U_Pomiar_pradu_napiecia_5.1
NetR585_2: R585.2 R586.2 R587.2 R588.2 U64_U_Pomiar_pradu_napiecia_6.2
NetR589_2: R589.2 R590.2 R591.2 R592.2 U64_U_Pomiar_pradu_napiecia_6.1
NetR595_2: R595.2 R596.2 R597.2 R598.2 U64_U_Pomiar_pradu_napiecia_2.1
NetR599_1: R599.1 U3_I2C_Bridge_2.19 U36_U_Translator_I2C1.6 U36_U_Translator_I2C2.6
NetR600_1: R600.1 R601.2 U58.1
NetR607_1: R607.1 U1.AA13
  other v2: 182.397,300.539
NetR612_1: R612.1 U34.29 | length 8.5
  L1 w0.254: U34.29@64.822,237.639 64.822,237.71 64.831,237.72 v22(64.831,239.097)
  L16 w0.254: v22(59.917,241.89) 59.917,241.114 60.285,240.746 60.915,240.746 61.483,240.178 64.683,240.178 64.831,240.029 v22(64.831,239.097)
NetR614_1: R614.1 U34.12 | length 6.9
  L1 w0.254: R614.1@59.692,230.712 63.088,230.712 64.11,231.734 64.666,231.734 64.815,231.882 64.815,232.984 64.82,232.989 64.82,233.137 U34.12@64.822,233.139
NetR621_1: R621.1 U37.29 | length 1.6
  L1 w0.254: R621.1@65.137,183.369 65.116,183.348 65.116,182.714 65.175,182.655 U37.29@65.175,181.817
NetR622_1: R622.1 U37.12 | length 1.4
  L1 w0.254: R622.1@65.175,175.893 U37.12@65.175,177.317
NetR628_1: R628.1 U38.12 | length 3
  L1 w0.254: v6(63.453,203.556) U38.12@63.453,204.214 ; R628.1@69.132,200.683 v6(69.132,201.631)
  L3 (Sign) w0.254: v6(63.453,203.556) 63.458,203.556 64.457,202.557
NetR644_1: R644.1 R645.2 U69.9
NetR648_2: R648.2 T25.3
NetR650_2: R650.2 T23.1 T24.3
NetR651_1: R651.1 T27.1 T28.3
NetR653_2: R653.2 T30.3
NetR655_1: R655.1 T29.1
NetR657_2: R657.2 T31.3
NetR658_1: R658.1 T31.1
NetR665_2: R665.2 U65.13 | length 2.9
  L1 w0.254: U65.13@38.76,206.158 38.76,207.602 39.014,207.856 R665.2@39.014,208.928
NetR677_1: R677.1 R682.2 U48.6 | length 2.9
  L1 w0.2: R677.1@44.716,192.933 R682.2@45.775,192.933 45.914,192.933 46.214,193.233 U48.6@47.527,193.233
NetR678_1: R678.1 R683.2 U48.5 | length 5.6
  L1 w0.2: R683.2@42.6,192.933 R678.1@43.658,192.933 43.658,193.501 43.89,193.733 U48.5@47.527,193.733
NetR679_1: R679.1 R684.2 U48.3 | length 2.9
  L1 w0.2: R684.2@44.716,195.033 R679.1@45.775,195.033 46.075,194.733 U48.3@47.527,194.733
NetR680_1: R680.1 R685.2 U48.4 | length 5.6
  L1 w0.2: R685.2@42.6,195.033 R680.1@43.658,195.033 43.658,194.466 43.89,194.233 U48.4@47.527,194.233
NetR681_2: R681.2 U48.10 | length 1.4
  L1 w0.2: U48.10@49.827,193.733 50.729,193.733 R681.2@51.105,194.109
NetR686_1: R686.1 U38.29 | length 0.6
  L1 w0.254: U38.29@63.453,208.714 v6@63.453,209.276
  other v6: 63.449,209.276
NetR689_2: R689.2 R690.2 U73.7 | length 10.7
  L1 w0.2: U73.7@151.644,349.484 153.033,349.484 v6(153.035,349.482)
  L1 w0.3: R690.2@159.652,348.062 160.213,348.062 ; v6(160.213,348.729) 160.213,348.062 ; R689.2@160.795,348.062 160.213,348.062
  L3 (Sign) w0.2: v6(153.035,349.482) v6@153.035,349.491
  L3 (Sign) w0.3: v6@153.035,349.491 153.797,348.729 v6(160.213,348.729)
NetR692_1: R692.1 S6.3 S6.4
NetR710_1: R710.1 R711.1 R712.2
NetR711_2: R711.2 U76.4
NetR713_1: R713.1 S7.1 S7.2
NetR714_2: R714.2 S7.3 S7.4
NetR736_1: R736.1 U1.AB13
  other v2: 183.397,300.539
NetR738_1: R738.1 R739.1 U35_I2C_Expander2.13
NetR740_1: R740.1 R741.1 U35_I2C_Expander2.12
NetR742_1: R742.1 R743.1 U35_I2C_Expander2.11
NetR753_1: R753.1 U3_I2C_Bridge.24
NetR754_1: R754.1 U35_I2C_Expander2.14
NetR758_1: R758.1 R759.1
NetR760_1: R760.1 R761.1
NetR762_1: R762.1 R763.1
NetR765_1: R765.1 U1.AE14
  other v2: 186.397,301.539
NetR766_1: R766.1 U1.AE13
  other v2: 186.397,300.539
NetR766_2: R766.2
NetR767_1: R767.1 U1.AC14
  other v2: 184.397,301.539
NetR767_2: R767.2
NetR768_1: R768.1
NetR769_1: R769.1
NetR770_1: R770.1
NetR771_1: R771.1
NetR836_2: R836.2 R838.1 U35_I2C_Expander_16.22
NetR837_2: R837.2 R840.1 U35_I2C_Expander_16.19
NetR839_2: R839.2 R841.1 U35_I2C_Expander_16.17
NetT22_3: T22.3 T23.2
NetT34_4: T34.4 U65.11 | length 14.6
  L1 w0.254: v6(37.846,218.796) 37.85,218.791 T34.4@38.377,218.791 ; U65.11@39.76,206.158 39.76,206.746 v6@40.514,207.5
  L3 (Sign) w0.254: v6(37.846,218.796) 37.846,213.779 40.526,211.099 v6(40.526,207.488)
NetT35_4: T35.4 U65.15 | length 8.6
  L1 w0.254: v6(36.36,212.471) T35.4@36.36,213.464 ; v6(36.71,206.368) 36.92,206.158 U65.15@37.76,206.158
  L3 (Sign) w0.254: v6(36.36,212.471) 36.093,212.204 36.093,206.985 v6(36.71,206.368)
NetTP7_I2C_Bridge_2_1: U3_I2C_Bridge_2.24
NetU1_AF11: U1.AF11
NetU1_AF12: U1.AF12
NetU1_AG11: U1.AG11
  other v2: 188.397,298.539
NetU1_AH11: U1.AH11
NetU1_AH12: U1.AH12
NetU1_AJ1: U1.AJ1
  other v2: 190.397,288.539
NetU1_AJ2: U1.AJ2
  other v2: 190.397,289.539
NetU1_AJ4: U1.AJ4
  other v2: 190.397,291.539
NetU1_AJ10: U1.AJ10
NetU1_AJ11: U1.AJ11
NetU1_AJ12: U1.AJ12
  other v2: 190.397,299.539
NetU1_AK4: U1.AK4
NetU1_AK10: U1.AK10
NetU1_AK11: U1.AK11
NetU1_D9: U1.D9
NetU1_D10: U1.D10
NetU1_G25: U1.G25
NetU1_G26: U1.G26
NetU1_G29: U1.G29
NetU1_G30: U1.G30
NetU1_H27: U1.H27
NetU1_H28: U1.H28
NetU1_J25: U1.J25
NetU1_J26: U1.J26
NetU3_I2C_Bridge_3_19: U3_I2C_Bridge_3.19 U36_U_Translator_I2C3.6 U36_U_Translator_I2C4.6
NetU3_I2C_Bridge_3_20: U3_I2C_Bridge_3.20 U36_U_Translator_I2C3.5 U36_U_Translator_I2C4.5
NetU24_SPI_bridge1_3: U24_SPI_bridge1.3 U25_SPI_bridge1.3 U25_SPI_bridge3.14 U26_SPI_bridge1.3 U27_SPI_bridge1.3 U28_SPI_bridge1.3
NetU24_SPI_bridge1_4: U24_SPI_bridge1.4 U25_SPI_bridge1.4 U25_SPI_bridge3.13 U26_SPI_bridge1.4 U27_SPI_bridge1.4 U28_SPI_bridge1.4
NetU24_SPI_bridge1_5: U24_SPI_bridge1.5 U25_SPI_bridge1.5 U25_SPI_bridge3.12 U26_SPI_bridge1.5 U27_SPI_bridge1.5 U28_SPI_bridge1.5
NetU24_SPI_bridge3_12: U24_SPI_bridge3.12
NetU24_SPI_bridge3_13: U24_SPI_bridge3.13
NetU24_SPI_bridge3_14: U24_SPI_bridge3.14
NetU27_SPI_bridge2_12: U27_SPI_bridge2.12
NetU27_SPI_bridge2_13: U27_SPI_bridge2.13
NetU27_SPI_bridge2_14: U27_SPI_bridge2.14
NetU27_SPI_bridge3_12: U27_SPI_bridge3.12
NetU27_SPI_bridge3_13: U27_SPI_bridge3.13
NetU27_SPI_bridge3_14: U27_SPI_bridge3.14
NetU28_SPI_bridge3_12: U28_SPI_bridge3.12
NetU28_SPI_bridge3_13: U28_SPI_bridge3.13
NetU28_SPI_bridge3_14: U28_SPI_bridge3.14
NetU35_I2C_Expander1_1: U35_I2C_Expander1.1
NetU35_I2C_Expander1_25: U35_I2C_Expander1.25
NetU35_I2C_Expander1_26: U35_I2C_Expander1.26
NetU35_I2C_Expander1_27: U35_I2C_Expander1.27
NetU35_I2C_Expander1_28: U35_I2C_Expander1.28
NetU35_I2C_Expander2_15: U35_I2C_Expander2.15
NetU35_I2C_Expander2_16: U35_I2C_Expander2.16
NetU35_I2C_Expander2_25: U35_I2C_Expander2.25
NetU35_I2C_Expander2_26: U35_I2C_Expander2.26
NetU35_I2C_Expander2_27: U35_I2C_Expander2.27
NetU35_I2C_Expander3_20: U35_I2C_Expander3.20
NetU35_I2C_Expander3_22: U35_I2C_Expander3.22
NetU35_I2C_Expander3_23: U35_I2C_Expander3.23
NetU35_I2C_Expander3_25: U35_I2C_Expander3.25
NetU35_I2C_Expander?_17: 
NetU35_I2C_Expander?_27: 
NetU35_I2C_Expander_10_27: 
NetU35_I2C_Expander_12_14: 
NetU35_I2C_Expander_12_26: 
NetU35_I2C_Expander_12_27: 
NetU35_I2C_Expander_13_2: 
NetU35_I2C_Expander_13_17: 
NetU35_I2C_Expander_13_18: 
NetU35_I2C_Expander_13_20: 
NetU35_I2C_Expander_13_26: 
NetU35_I2C_Expander_13_27: 
NetU35_I2C_Expander_14_17: 
NetU35_I2C_Expander_14_25: 
NetU35_I2C_Expander_14_26: 
NetU35_I2C_Expander_14_27: 
NetU35_I2C_Expander_15_4: 
NetU35_I2C_Expander_15_23: 
NetU35_I2C_Expander_15_24: 
NetU35_I2C_Expander_16_1: U35_I2C_Expander_16.1
NetU35_I2C_Expander_16_4: U35_I2C_Expander_16.4
NetU35_I2C_Expander_16_23: U35_I2C_Expander_16.23
NetU35_I2C_Expander_16_24: U35_I2C_Expander_16.24
NetU35_I2C_Expander_16_25: U35_I2C_Expander_16.25
NetU35_I2C_Expander_16_26: U35_I2C_Expander_16.26
NetU35_I2C_Expander_16_27: U35_I2C_Expander_16.27
NetU35_I2C_Expander_16_28: U35_I2C_Expander_16.28
NetU36_U_Translator_I2C1_8: U36_U_Translator_I2C1.8
NetU36_U_Translator_I2C4_8: U36_U_Translator_I2C4.8
NVME_C_RX_1_N: C718.1 U1.K28 | length 0.7
  L1 w0.116: U1.K28@171.397,315.539 v2(171.884,316.027)
NVME_C_RX_1_P: C717.1 U1.K27 | length 0.7
  L1 w0.116: U1.K27@171.397,314.539 v2(171.884,315.027)
NVME_C_RX_O_N: C677.1 U1.M28 | length 0.7
  L1 w0.116: 172.909,315.052 U1.M28@173.397,315.539
NVME_C_RX_O_P: C653.1 U1.M27 | length 0.7
  L1 w0.116: 172.909,314.052 U1.M27@173.397,314.539
NVME_C_TX_1_N: C716.1 U1.J30 | length 0.7
  L1 w0.116: v1(169.909,318.027) U1.J30@170.397,317.539
NVME_C_TX_1_P: C715.1 U1.J29 | length 0.7
  L1 w0.116: v1(169.909,317.027) U1.J29@170.397,316.539
NVME_C_TX_O_N: C651.1 U1.L30 | length 0.7
  L1 w0.116: v1(171.909,318.027) U1.L30@172.397,317.539
NVME_C_TX_O_P: C649.1 U1.L29 | length 0.7
  L1 w0.116: v1(171.909,317.027) U1.L29@172.397,316.539
NVMe_Rx_0_N: J27.47 R541.1
NVMe_Rx_0_P: J27.49 R541.2
NVMe_Rx_1_N: J27.35 R542.1
NVMe_Rx_1_P: J27.37 R542.2
NVMe_Tx_0_N: J27.41
NVMe_Tx_0_P: J27.43
NVMe_Tx_1_N: J27.29
NVMe_Tx_1_P: J27.31
OSC_500Out: C333.2 X2.10 | length 3.2
  L3 (Sign) w0.254: v25(198.844,270.281) v26(202.019,270.281)
  other v25: 202.019,270.281
  other v26: 198.844,270.281
Osc_in_Si53323_2_N: C343.2 R259.2 R261.2 R489.1 U32.6
Osc_in_Si53323_2_P: C342.2 R260.2 R262.2 R489.2 U32.7
OSC_Out_DIV_N: C343.1 R258.1 U33.11
OSC_Out_DIV_P: C342.1 R256.2 U33.10
PCIE0_CLK_N: J1_PCIE0.53
PCIE0_CLK_P: J1_PCIE0.55
PCIE0_En_DCDC: J1_PCIE0.36
PCIE0_Prsnt1: J1_PCIE0.12
PCIE0_Prsnt2: 
PCIE0_Reset: J1_PCIE0.32
PCIE0_SysRef_FPGA_N: U1.AG10
PCIE0_SysRef_FPGA_P: U1.AF10
PCIE0_SysRef_N: J1_PCIE0.52
PCIE0_SysRef_P: J1_PCIE0.50
PCIE1_CLK_N: J1_PCIE1.53
PCIE1_CLK_P: J1_PCIE1.55
PCIE1_En_DCDC: J1_PCIE1.36
PCIE1_Prsnt1: J1_PCIE1.12
PCIE1_Prsnt2: 
PCIE1_Reset: J1_PCIE1.32
PCIE1_SysRef_FPGA_N: U1.AK8
PCIE1_SysRef_FPGA_P: U1.AK9
PCIE1_SysRef_N: J1_PCIE1.52
PCIE1_SysRef_P: J1_PCIE1.50
PCIE2_CLK_N: J1_PCIE2.53 U14.6
PCIE2_CLK_P: J1_PCIE2.55 U14.7
PCIE2_En_DCDC: J1_PCIE2.36
PCIE2_Prsnt1: J1_PCIE2.12
PCIE2_Prsnt2: 
PCIE2_Reset: J1_PCIE2.32
PCIE2_SysRef_FPGA_N: U1.AJ9 U14.30
PCIE2_SysRef_FPGA_P: U1.AH9 U14.31
PCIE2_SysRef_N: J1_PCIE2.52 U14.3
PCIE2_SysRef_P: J1_PCIE2.50 U14.4
PCIE3_CLK_N: J1_PCIE3.53 U14.15
PCIE3_CLK_P: J1_PCIE3.55 U14.16
PCIE3_En_DCDC: J1_PCIE3.36
PCIE3_Prsnt1: J1_PCIE3.12
PCIE3_Prsnt2: 
PCIE3_Reset: J1_PCIE3.32
PCIE3_SysRef_FPGA_N: U1.AF7 U14.27
PCIE3_SysRef_FPGA_P: U1.AF8 U14.28
  other v2: 187.397,295.539
PCIE3_SysRef_N: J1_PCIE3.52 U14.9
PCIE3_SysRef_P: J1_PCIE3.50 U14.10
PCIE4_CLK_N: J1_PCIE4.53 U14.21
PCIE4_CLK_P: J1_PCIE4.55 U14.22
PCIE4_En_DCDC: J1_PCIE4.36
PCIE4_Prsnt1: J1_PCIE4.12
PCIE4_Prsnt2: 
PCIE4_Reset: J1_PCIE4.32
PCIE4_SysRef_FPGA_N: U1.AE8 U14.24
PCIE4_SysRef_FPGA_P: U1.AE9 U14.25
PCIE4_SysRef_N: J1_PCIE4.52 U14.18
PCIE4_SysRef_P: J1_PCIE4.50 U14.19
PCIe_Reset: R788.1
PDN: R498.2 U16.46
PDN_LMK05028: R499.1
PEDET: J27.61
PERST#: J27.50
PEwake: J27.54
PG1_1: R295.2 R836.1 R839.1 U37.27 | length 2
  L1 w0.254: U37.27@66.175,181.817 66.175,182.406 R295.2@67.169,183.4
PG1_2: R313.2 U38.27 | length 1.8
  L1 w0.254: U38.27@64.453,208.714 64.453,209.276 64.953,209.776 R313.2@64.953,210.304
PG1_TPS7A8801: R440.1 U35_I2C_Expander2.1 U61.17
PG2_2: R314.2 R837.1 U38.14 | length 1.6
  L1 w0.254: U38.14@64.453,204.214 64.455,204.212 64.455,203.6 64.623,203.432 R314.2@64.623,202.723
PG2_TPS7A8801: R441.1 U35_I2C_Expander2.28 U61.9
PG2_TPS7A8801_0V9: R676.1 U37.8 U70.9 U73.5
PG_1V0@1.5A: R834.2 U35_I2C_Expander_16.20 U51.5
PG_1V8@1.5A: R833.2 U35_I2C_Expander_16.21 U50.5
PG_2V5@1.5A: R392.1 U18.A2 U49.5
PG_48_20V: R835.2 U35_I2C_Expander_16.18 U65.19 | length 5
  L1 w0.254: 34.861,200.89 34.861,201.915 R835.2@34.847,201.93 v6(35.674,201.93) ; v6(35.671,203.818) U65.19@36.92,203.818
  L3 (Sign) w0.254: v6(35.671,203.818) 35.671,201.933 v6(35.674,201.93)
PG_DCDC_Low_curr: R832.2 U19.23 U35_I2C_Expander_16.3
PG_LT3042: R442.1 U62.4
PG_PS_LN_5V0_1: U35_I2C_Expander2.4
PG_PS_LTC6952_1: R431_U_5V_to_3V33.1 U35_I2C_Expander2.21 U59_U_5V_to_3V33.5
PG_PS_LTC6952_2: R431_U_5V_to_3V32.1 U35_I2C_Expander2.3 U59_U_5V_to_3V32.5
PG_PS_LTC6952_3: R431_U_5V_to_3V31.1 U35_I2C_Expander2.19 U59_U_5V_to_3V31.5
PG_VTT_RAM: R691.2 U35_I2C_Expander_16.2 U73.6
PGND: C595.1 C596.1 C597.1 C598.1 C694.1 C695.1 C696.1 C697.1 C698.1 C699.1 C700.1 C704.2 D3.2 D4.2 R324.1 R764.2 T35.1 T35.2 T35.3 U65.16 | length 33.5
  L1 w0.5: v1(32.55,212.65) T35.1@32.55,213.464 ; v1(33.82,212.65) T35.2@33.82,213.464 ; v1(35.09,212.65) T35.3@35.09,213.464 ; v1(37.032,210.162) C598.1@37.846,210.162 ; C699.1@51.994,200.664 v1(53.081,200.664) ; C699.1@51.994,201.387 v1(53.081,201.387) ; C696.1@51.994,202.554 v1(53.081,202.554) ; C696.1@51.994,203.278 v1(53.081,203.278) ; C697.1@51.994,204.444 v1(53.081,204.444) ; C697.1@51.994,205.168 v1(53.081,205.168) ; C695.1@51.994,206.335 v1(53.081,206.335) ; C695.1@51.994,207.059 v1(53.081,207.059) ; C698.1@51.994,208.225 v1(53.081,208.225) ; C698.1@51.994,208.949 v1(53.081,208.949)
  L16 w0.5: v5(27.345,227.151) C595.1@28.639,227.151 ; v5(28.639,225.857) C595.1@28.639,227.151 ; v5(29.932,227.151) C595.1@28.639,227.151 ; v5(30.586,223.896) D4.2@31.88,223.896 ; v5(31.88,222.602) D4.2@31.88,223.896 ; v5(31.88,225.19) D4.2@31.88,223.896 ; v5(33.174,223.896) D4.2@31.88,223.896 ; v5(40.454,223.832) D3.2@41.748,223.832 ; v5(41.748,222.539) D3.2@41.748,223.832 ; v5(41.748,225.126) D3.2@41.748,223.832 ; v5(43.041,223.832) D3.2@41.748,223.832 ; v5(48.998,225.107) R324.1@50.292,225.107 v5(50.292,223.813) ; v5(52.54,223.901) C596.1@52.54,225.195 v5(53.834,225.195)
PMU_GPI: J14.7 R784.1
PMU_GPI_1: J14.6 R785.1
PMU_GPI_2: J14.5 R786.1
PMU_GPI_3: J14.4 R787.1
PMU_GPI_5: J14.2 R789.1
PMU_GPO_0: J18.7 R790.1
PMU_GPO_1: J18.6 R791.1
PMU_GPO_2: J18.5 R792.1
PMU_GPO_3: J18.4 R793.1
PMU_GPO_4: J18.3 R794.1
PMU_GPO_5: J18.2 R795.1
Power1_In: P8.1 R448_U_Pomiar_pradu_napiecia_1.1 U64_U_Pomiar_pradu_napiecia_1.10
Power1_In_CM: R12.2 R448_U_Pomiar_pradu_napiecia_1.2 U5.7 U6.C3 U6.D3 U6.D4 U6.E3 U6.E4 U6.F3 U6.F4 U64_U_Pomiar_pradu_napiecia_1.8 U64_U_Pomiar_pradu_napiecia_1.9
  other v5: 46.94,171.336 47.599,172.073 46.939,172.838 48.188,172.838
  other v10: 48.36,174.6
Power2_In: P10.1 R448_U_Pomiar_pradu_napiecia_2.1 U64_U_Pomiar_pradu_napiecia_2.10
Power2_In_CM: R20.2 R448_U_Pomiar_pradu_napiecia_2.2 U5.2 U7.C3 U7.D3 U7.D4 U7.E3 U7.E4 U7.F3 U7.F4 U64_U_Pomiar_pradu_napiecia_2.8 U64_U_Pomiar_pradu_napiecia_2.9
  other v5: 46.939,177.161 48.188,177.161 47.599,177.926 46.94,178.663
  other v10: 48.36,175.4
Power4Charging: U6.C2 U6.D1 U6.D2 U6.E1 U6.E2 U6.F1 U6.F2 U7.C2 U7.D1 U7.D2 U7.E1 U7.E2 U7.F1 U7.F2
Power_3.3_1: C99.2 C100.2 C103.2 C104.2 C107.2 C124.2 C141.2 C145.2 C162.2 C179.2 C572.2 C573.2 FB8.1 FB9.1 FB10.1 FB11.1 FB12.1 FB14.1 FB16.1 FB18.1 FB20.1 FB22.1 R436.2 R440.2 U61.14 U61.15
Power_3.3_2: C108.2 C125.2 C142.2 C146.2 C163.2 C576.2 C577.2 FB13.1 FB15.1 FB17.1 FB19.1 FB21.1 R438.2 R441.2 U61.11 U61.12
Power_MUX_Status0: R13.2 U5.9 U35_I2C_Expander1.21 | length 1.8
  L1 w0.2: U5.9@49.86,174.25 50.769,174.25 50.927,174.091 R13.2@51.6,174.091
Power_MUX_Status1: R11.2 U4.9 U35_I2C_Expander1.20 | length 1.3
  L1 w0.2: U4.9@49.86,183.571 51.101,183.571 R11.2@51.11,183.563
Power_MUX_Status2: R630.2 U35_I2C_Expander1.4 U48.9 | length 1.1
  L1 w0.2: U48.9@49.827,193.233 50.736,193.233 R630.2@50.895,193.075
PS_MODE1: P2.3 R350.1 S1.2 U1.R19 U74.2
  other v2: 176.397,306.539
PS_POR: P3.2 R355.2 U1.N19 U74.1 U76.1 U77.6
  other v2: 174.397,306.539
PS_Reset: P4.1 R354.1 U1.P20 U77.4 U78.6
  other v2: 175.397,307.539
PSIO_VOLTAGE_3V3: U57.15
PWR_ExtIO_nReset: R755.1 U35_I2C_Expander1.14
